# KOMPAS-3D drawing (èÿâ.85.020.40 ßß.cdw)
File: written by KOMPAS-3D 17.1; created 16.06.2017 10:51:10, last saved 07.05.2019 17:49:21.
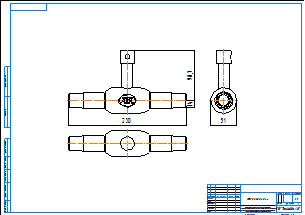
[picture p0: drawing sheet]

Sheet 1: A2, landscape

Title block, sheet 1: name: КШГ.85.020.40 сс; material: Внимание! Данный продукт является объектом авторского права ООО «Торговый Дом АДЛ». / Запрещается изменение, копирование, распространение / (в том числе путем копирования на другие сайты и ресурсы в Интернете) / или любое иное использование информации и объектов без предварительного / согласия правообладателя (ООО «Торговый Дом АДЛ»).; scale: 1:1; sheets: 1; organisation: ООО "Торговый дом АДЛ"; sheet format: A2; stored path: C:\Users\tra\Desktop\2д чертежи\Шаровые краны БИВАЛ\КШ_Бивал_серия_82_85\KOMPAS 2D\КШГ.85.020.40 сс.cdw

Views: Спереди 1, Проекционный вид 2, Проекционный вид 3
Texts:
  Klimkovich
  ADL
Dimensions and other numbers on the sheet: 230; 14; 98,7; 51; 1:1; 1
